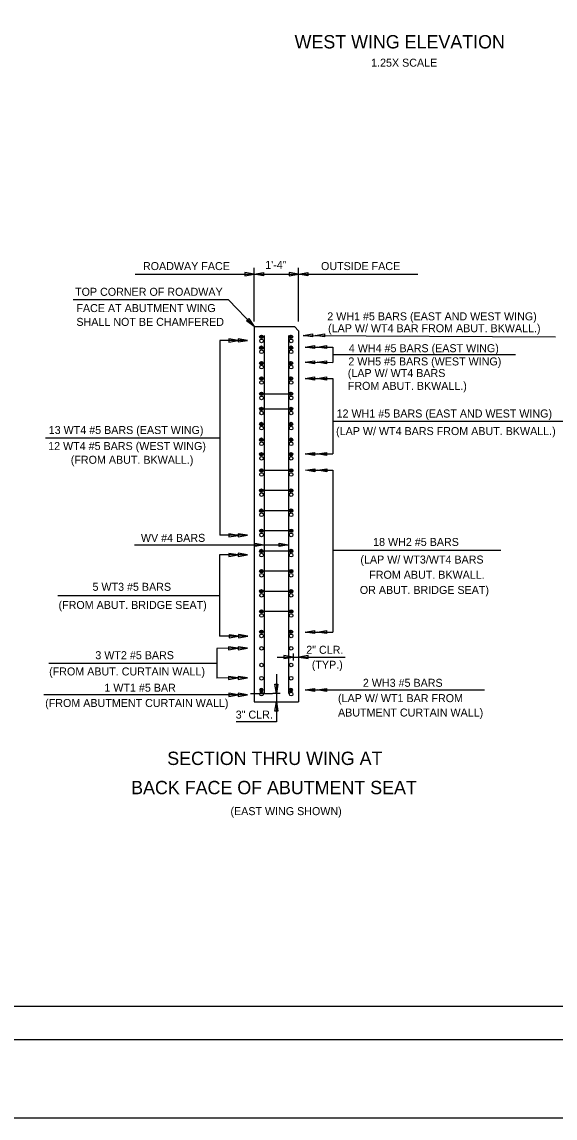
# Model space of a CAD drawing. Extents: x 2146833 to 2153191, y 139029 to 144029.
# Drawn here: x 2147180.8 to 2147212.7, y 143867.4 to 143933.1 of the extents above; entities that cross this region are included whole.
import ezdxf

# ---------------------------------------------------------------- set-up
doc = ezdxf.new("R2010")
doc.units = 0
for name, color, linetype in [('4', 7, 'Continuous'), ('PR_Bridge_Abutment', 7, 'Continuous'), ('PR_Bridge_Reinf', 7, 'Continuous'), ('PR_Dimensions', 7, 'Continuous'), ('PTX_36_LEADER', 7, 'Continuous'), ('SHT_Plot_Shape_Full', 7, 'Continuous'), ('SHT_Plot_Shape_Half', 7, 'Continuous'), ('SHT_Sheet_Border', 7, 'Continuous'), ('T', 7, 'Continuous'), ('T-Title', 7, 'Continuous')]:
    doc.layers.add(name, color=color, linetype=linetype)

# ---------------------------------------------------------------- blocks, each defined once
blk = doc.blocks.new('REINFORCEMENT')
at = {"layer": 'PTX_36_LEADER'}
blk.add_circle((0, 0.106), 0.106, dxfattribs=at)
blk.add_circle((0, 0.106), 0.106, dxfattribs=at)

msp = doc.modelspace()

# ---------------------------------------------------------------- linework, layer by layer
at = {"layer": '4'}
for p, q in [((2147194.673, 143914.001), (2147194.673, 143892.344)), ((2147194.673, 143892.337), (2147197.34, 143892.337))]:
    msp.add_line(p, q, dxfattribs=at)
at = {"layer": 'Defpoints'}
for p, q in [((2147195.1, 143910.814), (2147196.88, 143910.814)), ((2147195.1, 143909.907), (2147196.88, 143909.907)), ((2147195.121, 143906.236), (2147196.901, 143906.236)), ((2147195.121, 143905.027), (2147196.901, 143905.027)), ((2147195.121, 143903.819), (2147196.901, 143903.819)), ((2147195.121, 143902.611), (2147196.901, 143902.611)), ((2147195.121, 143901.402), (2147196.901, 143901.402)), ((2147195.121, 143900.194), (2147196.901, 143900.194)), ((2147195.121, 143898.986), (2147196.901, 143898.986)), ((2147195.121, 143897.777), (2147196.901, 143897.777)), ((2147194.46, 143892.837), (2147195.782, 143892.837))]:
    msp.add_line(p, q, dxfattribs=at)
at = {"layer": 'PR_Bridge_Abutment'}
for p, q in [((2147194.673, 143914.855), (2147197.087, 143914.855)), ((2147194.673, 143914.855), (2147194.673, 143892.337)), ((2147197.087, 143914.855), (2147197.34, 143914.602)), ((2147197.34, 143914.602), (2147197.34, 143892.337))]:
    msp.add_line(p, q, dxfattribs=at)
at = {"layer": 'PR_Bridge_Reinf'}
for p, q in [((2147195.274, 143914.317), (2147195.274, 143892.837)), ((2147196.739, 143914.317), (2147196.739, 143892.837))]:
    msp.add_line(p, q, dxfattribs=at)
for centre in [(2147195.12, 143913.991), (2147196.892, 143913.991), (2147195.12, 143913.339), (2147196.892, 143913.339), (2147195.12, 143912.416), (2147196.892, 143912.416), (2147195.12, 143911.494), (2147196.892, 143911.494), (2147195.12, 143910.571), (2147196.892, 143910.571), (2147195.12, 143909.664), (2147196.892, 143909.664), (2147195.12, 143908.757), (2147196.892, 143908.757), (2147195.12, 143907.82), (2147196.892, 143907.82), (2147195.12, 143906.944), (2147196.892, 143906.944), (2147195.12, 143905.975), (2147196.892, 143905.975), (2147195.12, 143904.766), (2147196.892, 143904.766), (2147195.12, 143903.558), (2147196.892, 143903.558), (2147195.12, 143902.35), (2147196.892, 143902.35), (2147195.12, 143901.141), (2147196.892, 143901.141), (2147195.12, 143899.933), (2147196.892, 143899.933), (2147195.12, 143898.725), (2147196.892, 143898.725), (2147195.12, 143897.516), (2147196.892, 143897.516), (2147195.12, 143896.292), (2147196.892, 143896.292), (2147195.12, 143895.544), (2147196.892, 143895.544), (2147195.12, 143894.544), (2147196.892, 143894.544), (2147195.12, 143893.753), (2147196.892, 143893.753), (2147195.12, 143892.8), (2147196.892, 143892.8)]:
    msp.add_circle(centre, 0.109, dxfattribs=at)
at = {"layer": 'PR_Dimensions'}
for p, q in [((2147194.673, 143915.154), (2147194.673, 143918.365)), ((2147197.34, 143915.154), (2147197.34, 143918.365)), ((2147187.538, 143917.994), (2147204.475, 143917.994)), ((2147193.143, 143916.45), (2147183.821, 143916.45)), ((2147194.673, 143914.862), (2147193.143, 143916.45)), ((2147197.612, 143914.32), (2147212.738, 143914.238)), ((2147194.28, 143914.019), (2147192.623, 143914.01)), ((2147192.623, 143914.01), (2147192.623, 143902.328)), ((2147197.735, 143913.619), (2147199.392, 143913.61)), ((2147199.392, 143913.61), (2147199.392, 143912.699)), ((2147210.325, 143913.154), (2147199.392, 143913.154)), ((2147197.735, 143912.708), (2147199.392, 143912.699)), ((2147197.735, 143911.735), (2147199.392, 143911.726)), ((2147199.392, 143911.726), (2147199.392, 143907.213)), ((2147213.636, 143909.158), (2147199.392, 143909.158)), ((2147182.167, 143908.169), (2147192.623, 143908.169)), ((2147197.735, 143907.211), (2147199.392, 143907.213)), ((2147197.874, 143906.228), (2147199.392, 143906.23)), ((2147199.392, 143906.23), (2147199.392, 143896.525)), ((2147194.28, 143902.326), (2147192.623, 143902.328)), ((2147187.5, 143901.758), (2147196.741, 143901.758)), ((2147194.141, 143901.153), (2147192.602, 143901.155)), ((2147192.602, 143901.155), (2147192.602, 143896.274)), ((2147209.446, 143901.406), (2147199.392, 143901.406)), ((2147182.908, 143898.714), (2147192.602, 143898.714)), ((2147197.729, 143896.524), (2147199.392, 143896.525)), ((2147194.287, 143896.276), (2147192.602, 143896.277)), ((2147194.28, 143895.547), (2147192.446, 143895.538)), ((2147192.446, 143895.538), (2147192.446, 143893.762)), ((2147197.003, 143895.234), (2147197.003, 143894.824)), ((2147182.37, 143894.65), (2147192.446, 143894.65)), ((2147196.055, 143895.021), (2147200.12, 143895.023)), ((2147194.28, 143893.771), (2147192.446, 143893.762)), ((2147196.008, 143894.002), (2147196.007, 143891.135)), ((2147194.28, 143892.755), (2147182.068, 143892.754)), ((2147196.227, 143892.837), (2147195.789, 143892.837)), ((2147197.735, 143893.047), (2147208.477, 143893.047)), ((2147196.007, 143891.135), (2147193.589, 143891.136))]:
    msp.add_line(p, q, dxfattribs=at)
for points in [[(2147194.113, 143917.901), (2147194.673, 143917.994), (2147194.113, 143918.088)], [(2147195.233, 143917.901), (2147194.673, 143917.994), (2147195.233, 143918.088)], [(2147196.78, 143917.901), (2147197.34, 143917.994), (2147196.78, 143918.088)], [(2147197.9, 143917.901), (2147197.34, 143917.994), (2147197.9, 143918.088)], [(2147194.352, 143915.33), (2147194.673, 143914.862), (2147194.218, 143915.2)], [(2147198.172, 143914.227), (2147197.612, 143914.32), (2147198.172, 143914.413)], [(2147198.891, 143914.227), (2147198.331, 143914.32), (2147198.891, 143914.413)], [(2147193.16, 143913.922), (2147193.72, 143914.016), (2147193.16, 143914.109)], [(2147193.72, 143913.925), (2147194.28, 143914.019), (2147193.72, 143914.112)], [(2147198.295, 143913.526), (2147197.735, 143913.619), (2147198.295, 143913.712)], [(2147199.014, 143913.526), (2147198.454, 143913.619), (2147199.014, 143913.712)], [(2147198.295, 143912.614), (2147197.735, 143912.708), (2147198.295, 143912.801)], [(2147199.014, 143912.614), (2147198.454, 143912.708), (2147199.014, 143912.801)], [(2147198.295, 143911.641), (2147197.735, 143911.735), (2147198.295, 143911.828)], [(2147199.014, 143911.641), (2147198.454, 143911.735), (2147199.014, 143911.828)], [(2147198.3, 143907.118), (2147197.74, 143907.211), (2147198.3, 143907.305)], [(2147199.019, 143907.118), (2147198.459, 143907.211), (2147199.019, 143907.305)], [(2147198.301, 143906.135), (2147197.741, 143906.228), (2147198.301, 143906.322)], [(2147199.02, 143906.135), (2147198.46, 143906.228), (2147199.02, 143906.322)], [(2147193.155, 143902.23), (2147193.715, 143902.323), (2147193.155, 143902.417)], [(2147193.715, 143902.233), (2147194.275, 143902.326), (2147193.715, 143902.42)], [(2147194.716, 143901.851), (2147195.276, 143901.758), (2147194.716, 143901.664)], [(2147196.181, 143901.851), (2147196.741, 143901.758), (2147196.181, 143901.664)], [(2147193.154, 143901.057), (2147193.714, 143901.15), (2147193.154, 143901.243)], [(2147193.714, 143901.06), (2147194.274, 143901.153), (2147193.714, 143901.246)], [(2147198.289, 143896.43), (2147197.729, 143896.524), (2147198.289, 143896.617)], [(2147199.008, 143896.43), (2147198.448, 143896.524), (2147199.008, 143896.617)], [(2147193.167, 143896.179), (2147193.727, 143896.273), (2147193.167, 143896.366)], [(2147193.727, 143896.182), (2147194.287, 143896.276), (2147193.727, 143896.369)], [(2147193.133, 143895.454), (2147193.693, 143895.547), (2147193.133, 143895.641)], [(2147193.713, 143895.453), (2147194.273, 143895.547), (2147193.713, 143895.64)], [(2147196.443, 143894.928), (2147197.003, 143895.022), (2147196.443, 143895.115)], [(2147197.902, 143895.115), (2147197.342, 143895.022), (2147197.902, 143894.928)], [(2147193.14, 143893.678), (2147193.7, 143893.772), (2147193.14, 143893.865)], [(2147193.72, 143893.678), (2147194.28, 143893.771), (2147193.72, 143893.864)], [(2147196.101, 143893.397), (2147196.008, 143892.837), (2147195.914, 143893.397)], [(2147198.295, 143892.954), (2147197.735, 143893.047), (2147198.295, 143893.141)], [(2147199.014, 143892.954), (2147198.454, 143893.047), (2147199.014, 143893.141)], [(2147193.16, 143892.661), (2147193.72, 143892.755), (2147193.16, 143892.848)], [(2147193.72, 143892.661), (2147194.28, 143892.755), (2147193.72, 143892.848)], [(2147195.914, 143891.777), (2147196.008, 143892.337), (2147196.101, 143891.777)]]:
    msp.add_lwpolyline(points, close=True, dxfattribs=at)
msp.add_lwpolyline([(2147197.902, 143895.022), (2147199.793, 143895.022)], dxfattribs=at)
for centre in [(2147195.121, 143914.252), (2147196.892, 143914.252), (2147195.121, 143913.6), (2147196.892, 143913.6), (2147195.121, 143912.677), (2147196.892, 143912.677), (2147195.121, 143911.755), (2147196.892, 143911.755), (2147195.121, 143910.832), (2147196.892, 143910.832), (2147195.121, 143909.925), (2147196.892, 143909.925), (2147195.121, 143909.018), (2147196.892, 143909.018), (2147195.121, 143908.08), (2147196.892, 143908.08), (2147195.121, 143907.205), (2147196.892, 143907.205), (2147195.121, 143906.236), (2147196.892, 143906.236), (2147195.121, 143905.027), (2147196.892, 143905.027), (2147195.121, 143903.819), (2147196.892, 143903.819), (2147195.121, 143902.611), (2147196.892, 143902.611), (2147195.121, 143901.402), (2147196.892, 143901.402), (2147195.121, 143900.194), (2147196.892, 143900.194), (2147195.121, 143898.986), (2147196.892, 143898.986), (2147195.121, 143897.777), (2147196.892, 143897.777), (2147195.121, 143896.553), (2147196.892, 143896.553), (2147195.121, 143893.02), (2147196.892, 143893.02)]:
    msp.add_circle(centre, 0.0533, dxfattribs=at)
for centre, start, end in [((2147195.121, 143914.252), 0, 180), ((2147195.121, 143914.252), 180, 0), ((2147196.892, 143914.252), 0, 180), ((2147196.892, 143914.252), 180, 0), ((2147195.121, 143913.6), 0, 180), ((2147195.121, 143913.6), 180, 0), ((2147196.892, 143913.6), 0, 180), ((2147196.892, 143913.6), 180, 0), ((2147195.121, 143912.677), 0, 180), ((2147195.121, 143912.677), 180, 0), ((2147196.892, 143912.677), 0, 180), ((2147196.892, 143912.677), 180, 0), ((2147195.121, 143911.755), 0, 180), ((2147195.121, 143911.755), 180, 0), ((2147196.892, 143911.755), 0, 180), ((2147196.892, 143911.755), 180, 0), ((2147195.121, 143910.832), 0, 180), ((2147196.892, 143910.832), 0, 180), ((2147195.121, 143910.832), 180, 0), ((2147196.892, 143910.832), 180, 0), ((2147195.121, 143909.925), 0, 180), ((2147195.121, 143909.925), 180, 0), ((2147196.892, 143909.925), 0, 180), ((2147196.892, 143909.925), 180, 0), ((2147195.121, 143909.018), 0, 180), ((2147195.121, 143909.018), 180, 0), ((2147196.892, 143909.018), 0, 180), ((2147196.892, 143909.018), 180, 0), ((2147195.121, 143908.08), 0, 180), ((2147195.121, 143908.08), 180, 0), ((2147196.892, 143908.08), 0, 180), ((2147196.892, 143908.08), 180, 0), ((2147195.121, 143907.205), 0, 180), ((2147195.121, 143907.205), 180, 0), ((2147196.892, 143907.205), 0, 180), ((2147196.892, 143907.205), 180, 0), ((2147195.121, 143906.236), 0, 180), ((2147196.892, 143906.236), 0, 180), ((2147195.121, 143906.236), 180, 0), ((2147196.892, 143906.236), 180, 0), ((2147195.121, 143905.027), 0, 180), ((2147195.121, 143905.027), 180, 0), ((2147196.892, 143905.027), 0, 180), ((2147196.892, 143905.027), 180, 0), ((2147195.121, 143903.819), 0, 180), ((2147195.121, 143903.819), 180, 0), ((2147196.892, 143903.819), 0, 180), ((2147196.892, 143903.819), 180, 0), ((2147195.121, 143902.611), 0, 180), ((2147195.121, 143902.611), 180, 0), ((2147196.892, 143902.611), 0, 180), ((2147196.892, 143902.611), 180, 0), ((2147195.121, 143901.402), 0, 180), ((2147195.121, 143901.402), 180, 0), ((2147196.892, 143901.402), 0, 180), ((2147196.892, 143901.402), 180, 0), ((2147195.121, 143900.194), 0, 180), ((2147195.121, 143900.194), 180, 0), ((2147196.892, 143900.194), 0, 180), ((2147196.892, 143900.194), 180, 0), ((2147195.121, 143898.986), 0, 180), ((2147196.892, 143898.986), 0, 180), ((2147195.121, 143898.986), 180, 0), ((2147196.892, 143898.986), 180, 0), ((2147195.121, 143897.777), 0, 180), ((2147195.121, 143897.777), 180, 0), ((2147196.892, 143897.777), 0, 180), ((2147196.892, 143897.777), 180, 0), ((2147195.121, 143896.553), 0, 180), ((2147195.121, 143896.553), 180, 0), ((2147196.892, 143896.553), 0, 180), ((2147196.892, 143896.553), 180, 0), ((2147195.121, 143893.02), 0, 180), ((2147195.121, 143893.02), 180, 0), ((2147196.892, 143893.02), 0, 180), ((2147196.892, 143893.02), 180, 0)]:
    msp.add_arc(centre, 0.0533, start, end, dxfattribs=at)
at = {"layer": 'SHT_Plot_Shape_Full'}
msp.add_lwpolyline([(2147114.94, 143963.364), (2147258.94, 143963.364), (2147258.94, 143867.364), (2147114.94, 143867.364)], close=True, dxfattribs=at)
at = {"layer": 'SHT_Plot_Shape_Half'}
msp.add_lwpolyline([(2147121.49, 143960.064), (2147257.49, 143960.064), (2147257.49, 143872.064), (2147121.49, 143872.064)], close=True, dxfattribs=at)
at = {"layer": 'SHT_Sheet_Border'}
msp.add_lwpolyline([(2147255.29, 143874.064), (2147129.29, 143874.064), (2147129.29, 143958.064), (2147255.29, 143958.064)], close=True, dxfattribs=at)

# ---------------------------------------------------------------- block references
at = {"layer": 'PR_Bridge_Reinf', "rotation": 152.99999999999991}
for p in [(2147195.157, 143914.328), (2147196.929, 143914.328), (2147195.157, 143913.676), (2147196.929, 143913.676), (2147195.157, 143912.753), (2147196.929, 143912.753), (2147195.157, 143911.831), (2147196.929, 143911.831), (2147195.157, 143910.908), (2147196.929, 143910.908), (2147195.157, 143910.001), (2147196.929, 143910.001), (2147195.157, 143909.094), (2147196.929, 143909.094), (2147195.157, 143908.156), (2147196.929, 143908.156), (2147195.157, 143907.281), (2147196.929, 143907.281), (2147195.157, 143906.312), (2147196.937, 143906.312), (2147195.157, 143905.103), (2147196.937, 143905.103), (2147195.157, 143903.895), (2147196.937, 143903.895), (2147195.157, 143902.687), (2147196.937, 143902.687), (2147195.157, 143901.478), (2147196.937, 143901.478), (2147195.157, 143900.27), (2147196.937, 143900.27), (2147195.157, 143899.062), (2147196.937, 143899.062), (2147195.157, 143897.853), (2147196.937, 143897.853), (2147195.157, 143896.629), (2147196.929, 143896.629)]:
    msp.add_blockref('REINFORCEMENT', p, dxfattribs=at)
at = {"layer": 'PR_Bridge_Reinf', "yscale": -1, "rotation": -152.99999999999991}
for p in [(2147195.157, 143892.944), (2147196.929, 143892.944)]:
    msp.add_blockref('REINFORCEMENT', p, dxfattribs=at)

# ---------------------------------------------------------------- texts
at = {"layer": 'Defpoints'}
msp.add_text('1.25X SCALE', height=0.48, dxfattribs=at).set_placement((2147201.683, 143930.441))
at = {"layer": 'T'}
for s, p in [('1\'-4"', (2147195.34, 143918.314)), ('ROADWAY FACE', (2147188.011, 143918.24)), ('OUTSIDE FACE', (2147198.681, 143918.24)), ('TOP CORNER OF ROADWAY', (2147183.943, 143916.696)), ('FACE AT ABUTMENT WING', (2147184.022, 143915.72)), ('2 WH1 #5 BARS (EAST AND WEST WING)', (2147199.055, 143915.224)), ('SHALL NOT BE CHAMFERED', (2147184.022, 143914.892)), ('(LAP W/ WT4 BAR FROM ABUT. BKWALL.)', (2147199.103, 143914.51)), ('4 WH4 #5 BARS (EAST WING)', (2147200.347, 143913.312)), ('2 WH5 #5 BARS (WEST WING)', (2147200.319, 143912.519)), ('(LAP W/ WT4 BARS ', (2147200.285, 143911.822)), ('FROM ABUT. BKWALL.)', (2147200.285, 143911.054)), ('12 WH1 #5 BARS (EAST AND WEST WING)', (2147199.615, 143909.395)), ('13 WT4 #5 BARS (EAST WING)', (2147182.364, 143908.406)), ('(LAP W/ WT4 BARS FROM ABUT. BKWALL.)', (2147199.584, 143908.341)), ('12 WT4 #5 BARS (WEST WING)', (2147182.332, 143907.443)), ('(FROM ABUT. BKWALL.)', (2147183.686, 143906.619)), ('WV #4 BARS', (2147187.889, 143901.934)), ('18 WH2 #5 BARS', (2147201.803, 143901.689)), ('(LAP W/ WT3/WT4 BARS', (2147201.04, 143900.633)), ('FROM ABUT. BKWALL.', (2147201.57, 143899.721)), ('5 WT3 #5 BARS', (2147184.987, 143898.998)), ('OR ABUT. BRIDGE SEAT)', (2147201.006, 143898.809)), ('(FROM ABUT. BRIDGE SEAT)', (2147182.952, 143897.909)), ('3 WT2 #5 BARS', (2147185.158, 143894.896)), ('2" CLR.', (2147197.795, 143895.218)), ('(FROM ABUT. CURTAIN WALL)', (2147182.388, 143893.92)), ('(TYP.)', (2147198.129, 143894.323)), ('1 WT1 #5 BAR', (2147185.699, 143892.945)), ('2 WH3 #5 BARS', (2147201.189, 143893.238)), ('(FROM ABUTMENT CURTAIN WALL)', (2147182.151, 143892.027)), ('(LAP W/ WT1 BAR FROM', (2147199.699, 143892.319)), ('3" CLR.', (2147193.569, 143891.331)), ('ABUTMENT CURTAIN WALL)', (2147199.699, 143891.455)), ('(EAST WING SHOWN)', (2147193.254, 143885.539))]:
    msp.add_text(s, height=0.48, dxfattribs=at).set_placement(p)
at = {"layer": 'T-Title'}
for s, p in [('WEST WING ELEVATION', (2147197.098, 143931.536)), ('SECTION THRU WING AT', (2147189.466, 143888.547)), ('BACK FACE OF ABUTMENT SEAT', (2147187.303, 143886.795))]:
    msp.add_text(s, height=0.8, dxfattribs=at).set_placement(p)

doc.saveas('drawing.dxf')
